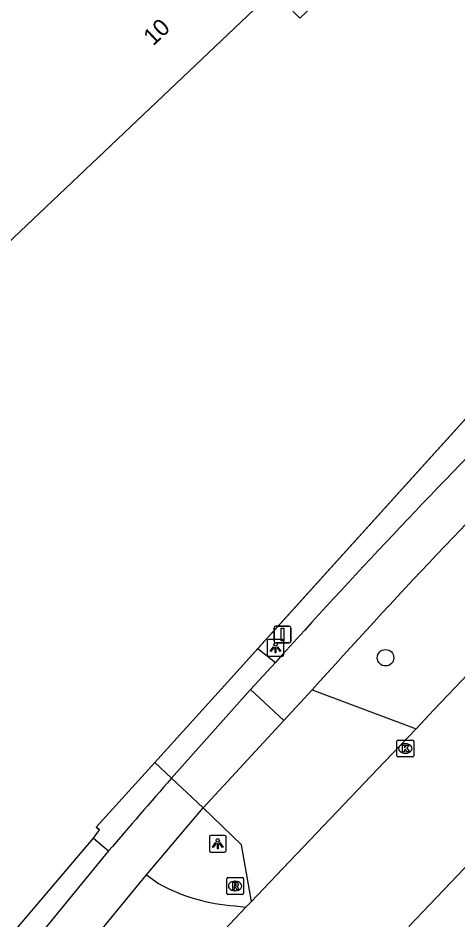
# Model space of a CAD drawing. Extents: x 156141 to 158132, y 385651 to 388399.
# Drawn here: x 156888.7 to 156914.8, y 387219.7 to 387273.3 of the extents above; entities that cross this region are included whole.
import ezdxf

# ---------------------------------------------------------------- set-up
doc = ezdxf.new("R2010")
doc.units = 0
for name, color, linetype in [('IMGEO_Berm_groen', 7, 'Continuous'), ('IMGEO_Boom', 7, 'Continuous'), ('IMGEO_Fietspad_gesloten', 7, 'Continuous'), ('IMGEO_Groenvoorziening', 7, 'Continuous'), ('IMGEO_Hek', 7, 'Continuous'), ('IMGEO_Kolk', 7, 'Continuous'), ('IMGEO_Lichtpunt', 7, 'Continuous'), ('IMGEO_Pand', 7, 'Continuous'), ('IMGEO_Pand_nummerreeks', 7, 'Continuous'), ('IMGEO_Rijbaan_lokaal_gesloten', 7, 'Continuous'), ('IMGEO_Rijbaan_lokaal_open', 7, 'Continuous'), ('IMGEO_Rioolput', 7, 'Continuous'), ('IMGEO_Verkeersbordpaal', 7, 'Continuous')]:
    doc.layers.add(name, color=color, linetype=linetype)

msp = doc.modelspace()

# ---------------------------------------------------------------- linework, layer by layer
at = {"layer": 'IMGEO_Berm_groen'}
msp.add_lwpolyline([(156902.901, 387235.828), (156933.171, 387269.321), (156932.23, 387270.289), (156921.587, 387281.238), (156915.865, 387288.761), (156908.089, 387303.369), (156905.42, 387307.278), (156895.183, 387318.713)], dxfattribs=at)
at = {"layer": 'IMGEO_Boom'}
msp.add_circle((156910.484, 387235.273), 0.489, dxfattribs=at)
at = {"layer": 'IMGEO_Fietspad_gesloten'}
for points in [[(156904.446, 387231.549), (156902.453, 387233.379)], [(156899.657, 387226.346), (156897.771, 387228.115)], [(156896.278, 387222.376), (156899.657, 387226.346)]]:
    msp.add_lwpolyline(points, dxfattribs=at)
for centre, radius, start, end in [((157231.352, 386940.491), 440.372, 135.34517, 138.02939), ((157246.366, 386927.372), 457.599, 135.29407, 138.03304), ((157262.899, 386908.23), 485.432, 138.77871, 139.45314)]:
    msp.add_arc(centre, radius, start, end, dxfattribs=at)
at = {"layer": 'IMGEO_Groenvoorziening'}
msp.add_lwpolyline([(156893.124, 387224.546), (156893.489, 387225.043), (156893.292, 387225.201), (156896.771, 387229.052)], dxfattribs=at)
at = {"layer": 'IMGEO_Hek'}
for points in [[(156901.471, 387234.246), (156933.171, 387269.321)], [(156896.771, 387229.052), (156901.471, 387234.246)], [(156896.771, 387229.052), (156893.292, 387225.201)], [(156893.292, 387225.201), (156893.489, 387225.043)]]:
    msp.add_lwpolyline(points, dxfattribs=at)
at = {"layer": 'IMGEO_Kolk'}
for p, q in [((156911.162, 387229.455), (156911.162, 387230.307)), ((156911.237, 387230.381), (156912.089, 387230.381)), ((156911.65, 387230.161), (156911.675, 387230.161)), ((156912.163, 387230.307), (156912.163, 387229.455)), ((156912.089, 387229.381), (156911.237, 387229.381)), ((156911.673, 387229.601), (156911.648, 387229.601))]:
    msp.add_line(p, q, dxfattribs=at)
for points in [[(156911.162, 387229.455), (156911.162, 387230.307)], [(156911.237, 387230.381), (156912.089, 387230.381)], [(156911.483, 387230.081), (156911.606, 387230.081), (156911.606, 387229.93), (156911.736, 387230.081), (156911.9, 387230.081), (156911.754, 387229.93), (156911.907, 387229.681), (156911.755, 387229.681), (156911.67, 387229.845), (156911.606, 387229.778), (156911.606, 387229.681), (156911.483, 387229.681), (156911.483, 387230.081)], [(156912.163, 387230.307), (156912.163, 387229.455)], [(156912.089, 387229.381), (156911.237, 387229.381)]]:
    msp.add_lwpolyline(points, dxfattribs=at)
for centre, start, end in [((156911.239, 387230.305), 91.552, 178.448), ((156911.239, 387230.305), 91.552, 178.448), ((156912.087, 387230.305), 1.552, 88.448), ((156912.087, 387230.305), 1.552, 88.448), ((156911.239, 387229.457), 181.552, 268.448), ((156911.239, 387229.457), 181.552, 268.448), ((156912.087, 387229.457), 271.552, 358.448), ((156912.087, 387229.457), 271.552, 358.448)]:
    msp.add_arc(centre, 0.0765, start, end, dxfattribs=at)
for centre, major_axis, ratio, start_param, end_param in [((156911.649, 387229.881), (-0.387, 0.002), 0.722429, 4.712389, 7.853982), ((156911.674, 387229.881), (-0.39, 0.002), 0.717154, 1.570796, 4.712389)]:
    msp.add_ellipse(centre, major_axis=major_axis, ratio=ratio, start_param=start_param, end_param=end_param, dxfattribs=at)
at = {"layer": 'IMGEO_Lichtpunt'}
for p, q in [((156904.353, 387236.361), (156903.545, 387236.361)), ((156904.353, 387236.361), (156903.545, 387236.361)), ((156903.451, 387236.266), (156903.451, 387235.459)), ((156903.451, 387236.266), (156903.451, 387235.459)), ((156904.447, 387235.459), (156904.447, 387236.266)), ((156904.447, 387235.459), (156904.447, 387236.266)), ((156903.545, 387235.365), (156904.353, 387235.365)), ((156903.545, 387235.365), (156904.353, 387235.365)), ((156900.018, 387224.626), (156900.018, 387223.819)), ((156900.018, 387224.626), (156900.018, 387223.819)), ((156900.92, 387224.721), (156900.112, 387224.721)), ((156900.92, 387224.721), (156900.112, 387224.721)), ((156901.014, 387223.819), (156901.014, 387224.626)), ((156901.014, 387223.819), (156901.014, 387224.626)), ((156900.112, 387223.725), (156900.92, 387223.725)), ((156900.112, 387223.725), (156900.92, 387223.725))]:
    msp.add_line(p, q, dxfattribs=at)
for points in [[(156903.825, 387235.93), (156903.864, 387235.902), (156903.676, 387235.64), (156903.638, 387235.667), (156903.825, 387235.93)], [(156903.927, 387235.882), (156903.974, 387235.882), (156903.974, 387235.56), (156903.927, 387235.56), (156903.927, 387235.882)], [(156904.037, 387235.902), (156904.075, 387235.929), (156904.262, 387235.667), (156904.223, 387235.639), (156904.037, 387235.902)], [(156900.392, 387224.29), (156900.431, 387224.262), (156900.243, 387224), (156900.205, 387224.027), (156900.392, 387224.29)], [(156900.494, 387224.242), (156900.541, 387224.242), (156900.541, 387223.92), (156900.494, 387223.92), (156900.494, 387224.242)], [(156900.604, 387224.262), (156900.642, 387224.289), (156900.829, 387224.027), (156900.79, 387223.999), (156900.604, 387224.262)]]:
    msp.add_lwpolyline(points, dxfattribs=at)
for centre in [(156903.95, 387236.064), (156900.517, 387224.424)]:
    msp.add_circle(centre, 0.0994, dxfattribs=at)
for centre, start, end in [((156903.545, 387236.266), 90, 180), ((156903.545, 387236.266), 90, 180), ((156904.353, 387236.266), 0, 90), ((156904.353, 387236.266), 0, 90), ((156903.545, 387235.459), 180, 270), ((156903.545, 387235.459), 180, 270), ((156904.353, 387235.459), 270, 0), ((156904.353, 387235.459), 270, 360), ((156900.112, 387224.626), 90, 180), ((156900.112, 387224.626), 90, 180), ((156900.92, 387224.626), 0, 90), ((156900.92, 387224.626), 0, 90), ((156900.112, 387223.819), 180, 270), ((156900.112, 387223.819), 180, 270), ((156900.92, 387223.819), 270, 0), ((156900.92, 387223.819), 270, 360)]:
    msp.add_arc(centre, 0.0946, start, end, dxfattribs=at)
at = {"layer": 'IMGEO_Pand'}
msp.add_lwpolyline([(156865.585, 387277.23), (156884.532, 387295.217), (156882.975, 387296.854), (156891.996, 387305.435), (156914.425, 387281.872), (156905.392, 387273.281), (156903.825, 387274.901), (156884.891, 387256.928), (156875.318, 387247.841), (156856.013, 387268.143), (156865.585, 387277.23)], dxfattribs=at)
at = {"layer": 'IMGEO_Rijbaan_lokaal_gesloten'}
for points in [[(156911.876, 387219.298), (156930.437, 387238.77), (156930.223, 387238.975), (156938.979, 387248.204)], [(156924.829, 387244.202), (156913.363, 387232.176), (156912.298, 387231.059)], [(156912.298, 387231.059), (156910.423, 387229.092), (156903.978, 387222.333), (156902.515, 387220.799)], [(156888.871, 387213.348), (156896.278, 387222.376)], [(156896.278, 387222.376), (156896.992, 387221.858)], [(156902.515, 387220.799), (156902.19, 387220.458)], [(156902.19, 387220.458), (156890.27, 387207.768)], [(156901.541, 387220.528), (156902.19, 387220.458)]]:
    msp.add_lwpolyline(points, dxfattribs=at)
msp.add_arc((156902.262, 387231.437), 10.933, 241.1843, 266.2208, dxfattribs=at)
at = {"layer": 'IMGEO_Rijbaan_lokaal_open'}
for points in [[(156896.771, 387229.052), (156901.471, 387234.246), (156902.901, 387235.828)], [(156902.901, 387235.828), (156903.941, 387234.99)], [(156902.453, 387233.379), (156903.941, 387234.99)], [(156897.771, 387228.115), (156902.453, 387233.379)], [(156906.127, 387233.37), (156904.446, 387231.549)], [(156906.127, 387233.37), (156912.298, 387231.059)], [(156899.657, 387226.346), (156904.446, 387231.549)], [(156896.771, 387229.052), (156897.771, 387228.115)], [(156902.515, 387220.799), (156901.919, 387224.164), (156899.657, 387226.346)], [(156885.747, 387215.869), (156893.124, 387224.546)], [(156893.124, 387224.546), (156894.031, 387223.795)], [(156894.031, 387223.795), (156886.802, 387214.994)]]:
    msp.add_lwpolyline(points, dxfattribs=at)
at = {"layer": 'IMGEO_Rioolput'}
for p, q in [((156901.046, 387221.285), (156901.046, 387222.137)), ((156901.121, 387222.211), (156901.973, 387222.211)), ((156901.534, 387221.991), (156901.559, 387221.991)), ((156902.047, 387222.137), (156902.047, 387221.285)), ((156901.557, 387221.431), (156901.532, 387221.431)), ((156901.973, 387221.211), (156901.121, 387221.211))]:
    msp.add_line(p, q, dxfattribs=at)
for points in [[(156901.046, 387221.285), (156901.046, 387222.137)], [(156901.121, 387222.211), (156901.973, 387222.211)], [(156901.635, 387221.909), (156901.383, 387221.911), (156901.383, 387221.511)], [(156902.047, 387222.137), (156902.047, 387221.285)], [(156901.383, 387221.511), (156901.507, 387221.511), (156901.507, 387221.673), (156901.518, 387221.673)], [(156901.561, 387221.83), (156901.507, 387221.83), (156901.507, 387221.749)], [(156901.507, 387221.749), (156901.559, 387221.749)], [(156901.565, 387221.644), (156901.636, 387221.511), (156901.776, 387221.511), (156901.711, 387221.637)], [(156901.973, 387221.211), (156901.121, 387221.211)]]:
    msp.add_lwpolyline(points, dxfattribs=at)
for centre, radius, start, end in [((156901.123, 387222.135), 0.0765, 91.552, 178.448), ((156901.123, 387222.135), 0.0765, 91.552, 178.448), ((156901.634, 387221.799), 0.109, 350.3612, 89.416), ((156901.971, 387222.135), 0.0765, 1.552, 88.448), ((156901.971, 387222.135), 0.0765, 1.552, 88.448), ((156901.517, 387221.62), 0.0533, 26.0293, 88.6989), ((156901.543, 387221.938), 0.19, 274.7715, 282.9687), ((156901.567, 387221.734), 0.0964, 77.0061, 93.1865), ((156901.581, 387221.791), 0.0378, 276.6634, 79.6772), ((156901.632, 387221.799), 0.112, 277.5842, 350.9817), ((156901.616, 387221.584), 0.108, 29.5134, 73.7905), ((156901.123, 387221.287), 0.0765, 181.552, 268.448), ((156901.123, 387221.287), 0.0765, 181.552, 268.448), ((156901.971, 387221.287), 0.0765, 271.552, 358.448), ((156901.971, 387221.287), 0.0765, 271.552, 358.448)]:
    msp.add_arc(centre, radius, start, end, dxfattribs=at)
for centre, major_axis, ratio, start_param, end_param in [((156901.533, 387221.711), (-0.387, 0.002), 0.722429, 4.712389, 7.853982), ((156901.558, 387221.711), (-0.39, 0.002), 0.717154, 1.570796, 4.712389)]:
    msp.add_ellipse(centre, major_axis=major_axis, ratio=ratio, start_param=start_param, end_param=end_param, dxfattribs=at)
at = {"layer": 'IMGEO_Verkeersbordpaal'}
for p, q in [((156903.863, 387236.25), (156903.863, 387237.05)), ((156903.863, 387237.05), (156903.863, 387236.25)), ((156903.963, 387237.15), (156904.753, 387237.15)), ((156904.753, 387237.15), (156903.963, 387237.15)), ((156904.853, 387237.05), (156904.853, 387236.25)), ((156904.853, 387236.25), (156904.853, 387237.05)), ((156904.753, 387236.15), (156903.963, 387236.15)), ((156903.963, 387236.15), (156904.753, 387236.15))]:
    msp.add_line(p, q, dxfattribs=at)
msp.add_lwpolyline([(156904.283, 387237.025), (156904.433, 387237.025), (156904.433, 387236.275), (156904.283, 387236.275), (156904.283, 387237.025)], dxfattribs=at)
for centre, start, end in [((156903.963, 387237.05), 90, 180), ((156903.963, 387237.05), 90, 180), ((156904.753, 387237.05), 0, 90), ((156904.753, 387237.05), 360, 90), ((156903.963, 387236.25), 180, 270), ((156903.963, 387236.25), 180, 270), ((156904.753, 387236.25), 270, 0), ((156904.753, 387236.25), 270, 0)]:
    msp.add_arc(centre, 0.1, start, end, dxfattribs=at)

# ---------------------------------------------------------------- texts
at = {"layer": 'IMGEO_Pand_nummerreeks'}
msp.add_text('10', height=1, rotation=43.5084, dxfattribs=at).set_placement((156896.678, 387271.591))

doc.saveas('drawing.dxf')
